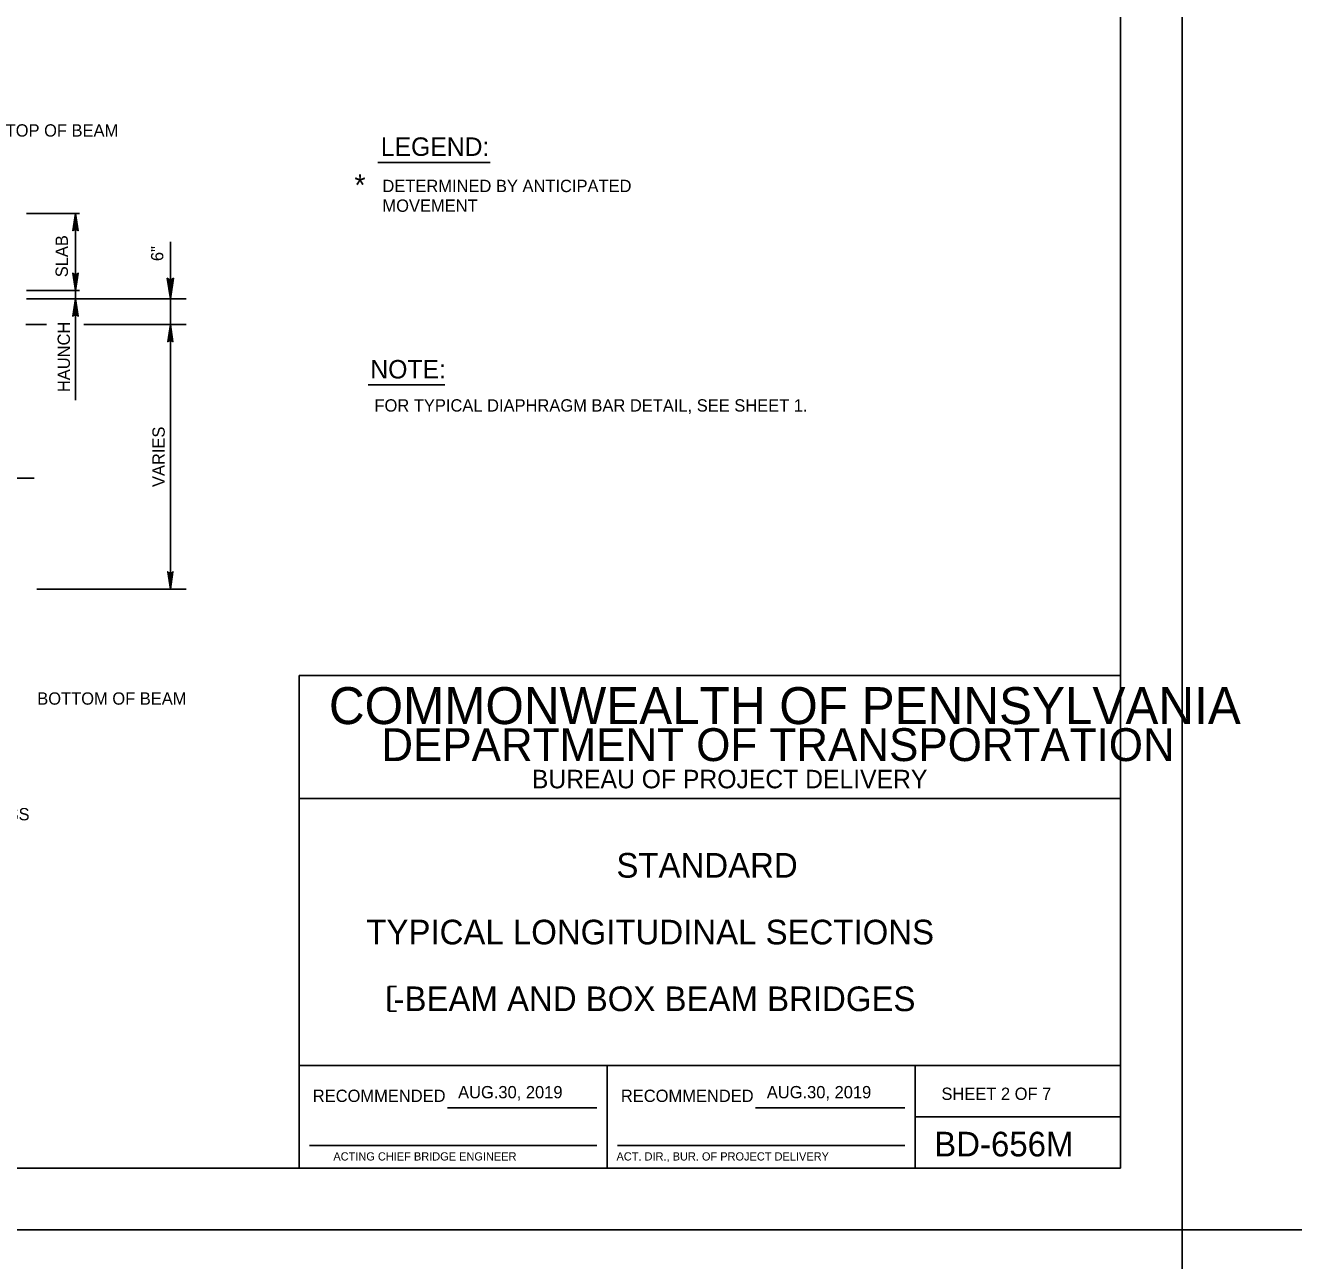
# Model space of a CAD drawing. Extents: x 638653 to 642302, y 298557 to 300414.
# Drawn here: x 640382.5 to 640691.3, y 299737 to 300037.8 of the extents above; entities that cross this region are included whole.
import ezdxf

# ---------------------------------------------------------------- set-up
doc = ezdxf.new("R2010")
doc.units = 0
doc.layers.add('1', color=7, linetype='Continuous')
doc.layers.add('PLT-BNDY', color=7, linetype='Continuous')

msp = doc.modelspace()

# ---------------------------------------------------------------- linework, layer by layer
at = {"layer": '1'}
for p, q in [((640649.16, 300323.52), (640649.16, 299759.52)), ((640468.35, 300004.41), (640495.64, 300004.41)), ((640395.69, 299991.97), (640382.79, 299991.97)), ((640394.72, 299991.97), (640394.72, 299946.54)), ((640417.81, 299985.1), (640417.81, 299971.16)), ((640395.69, 299973.22), (640382.79, 299973.22)), ((640421.66, 299971.16), (640382.79, 299971.16)), ((640417.81, 299971.16), (640417.81, 299964.97)), ((640387.69, 299964.97), (640382.62, 299964.97)), ((640421.66, 299964.97), (640396.76, 299964.97)), ((640417.81, 299964.97), (640417.81, 299900.54)), ((640484.66, 299950.27), (640465.99, 299950.27)), ((640384.63, 299927.53), (640350.17, 299927.53)), ((640649.16, 299923.18), (640649.16, 299872.29)), ((640649.16, 299923.18), (640649.16, 299918.86)), ((640421.66, 299900.54), (640385.34, 299900.54)), ((640649.16, 299879.52), (640449.16, 299879.52)), ((640449.16, 299879.52), (640449.16, 299759.52)), ((640649.16, 299879.52), (640473.77, 299879.52)), ((640649.16, 299879.52), (640473.77, 299879.52)), ((640649.16, 299759.52), (640649.16, 299879.52)), ((640649.16, 299849.52), (640449.16, 299849.52)), ((640471, 299803.77), (640472.88, 299803.77)), ((640471, 299797.77), (640472.88, 299797.77)), ((640649.16, 299784.52), (640449.16, 299784.52)), ((640524.16, 299759.52), (640524.16, 299784.52)), ((640599.16, 299784.52), (640599.16, 299759.52)), ((640485.25, 299774.24), (640521.66, 299774.24)), ((640560.25, 299774.24), (640596.66, 299774.24)), ((640599.16, 299772.02), (640649.16, 299772.02)), ((640451.66, 299765.02), (640521.66, 299765.02)), ((640526.66, 299765.02), (640596.66, 299765.02)), ((640649.16, 299759.52), (639863.16, 299759.52)), ((640449.16, 299759.52), (640649.16, 299759.52)), ((640664.16, 299744.52), (640664.16, 299744.52))]:
    msp.add_line(p, q, dxfattribs=at)
for points in [[(640394.25, 299987.91), (640394.56, 299988.07), (640394.72, 299991.97), (640394.25, 299987.91), (640394.09, 299987.76), (640394.72, 299991.97), (640394.87, 299988.07), (640395.19, 299987.91), (640394.72, 299991.97), (640395.34, 299987.76), (640395.19, 299987.91)], [(640395.19, 299977.29), (640394.87, 299977.13), (640394.72, 299973.22), (640395.19, 299977.29), (640395.34, 299977.44), (640394.72, 299973.22), (640394.56, 299977.13), (640394.25, 299977.29), (640394.72, 299973.22), (640394.09, 299977.44), (640394.25, 299977.29)], [(640418.37, 299976.04), (640417.99, 299975.85), (640417.81, 299971.16), (640418.37, 299976.04), (640418.56, 299976.22), (640417.81, 299971.16), (640417.62, 299975.85), (640417.24, 299976.04), (640417.81, 299971.16), (640417.06, 299976.22), (640417.24, 299976.04)], [(640418.28, 299975.22), (640417.96, 299975.07), (640417.81, 299971.16), (640418.28, 299975.22), (640418.43, 299975.38), (640417.81, 299971.16), (640417.65, 299975.07), (640417.34, 299975.22), (640417.81, 299971.16), (640417.18, 299975.38), (640417.34, 299975.22)], [(640394.25, 299967.1), (640394.56, 299967.26), (640394.72, 299971.16), (640394.25, 299967.1), (640394.09, 299966.94), (640394.72, 299971.16), (640394.87, 299967.26), (640395.19, 299967.1), (640394.72, 299971.16), (640395.34, 299966.94), (640395.19, 299967.1)], [(640417.34, 299960.91), (640417.65, 299961.07), (640417.81, 299964.97), (640417.34, 299960.91), (640417.18, 299960.76), (640417.81, 299964.97), (640417.96, 299961.07), (640418.28, 299960.91), (640417.81, 299964.97), (640418.43, 299960.76), (640418.28, 299960.91)], [(640418.28, 299904.6), (640417.96, 299904.45), (640417.81, 299900.54), (640418.28, 299904.6), (640418.43, 299904.76), (640417.81, 299900.54), (640417.65, 299904.45), (640417.34, 299904.6), (640417.81, 299900.54), (640417.18, 299904.76), (640417.34, 299904.6)]]:
    msp.add_lwpolyline(points, dxfattribs=at)
at = {"layer": 'PLT-BNDY'}
for points in [[(639823.16, 300338.52), (640664.16, 300338.52), (640664.16, 299744.52), (639823.16, 299744.52)], [(640664.16, 300338.52), (641505.16, 300338.52), (641505.16, 299744.52), (640664.16, 299744.52)], [(639823.16, 299744.52), (640664.16, 299744.52), (640664.16, 299150.52), (639823.16, 299150.52)], [(640664.16, 299744.52), (641505.16, 299744.52), (641505.16, 299150.52), (640664.16, 299150.52)]]:
    msp.add_lwpolyline(points, close=True, dxfattribs=at)

# ---------------------------------------------------------------- texts
at = {"layer": '1'}
for s, height, p in [('TOP OF BEAM', 2.9999, (640377.71, 300010.69)), ('LEGEND:', 4.5, (640469.05, 300005.99)), ('*', 5.18, (640462.63, 299996.32)), ('DETERMINED BY ANTICIPATED', 3, (640469.44, 299997.18)), ('MOVEMENT', 3, (640469.44, 299992.38)), ('NOTE:', 4.5, (640466.5, 299951.8)), ('FOR TYPICAL DIAPHRAGM BAR DETAIL, SEE SHEET 1.', 3, (640467.5, 299943.74)), ('BOTTOM OF BEAM', 2.9999, (640385.41, 299872.38)), ('COMMONWEALTH OF PENNSYLVANIA', 9, (640456.41, 299867.65)), ('DEPARTMENT OF TRANSPORTATION', 8.0002, (640469.16, 299858.65)), ('BUREAU OF PROJECT DELIVERY', 4.5, (640505.82, 299852.02)), ('FOR SPANS WITH VERTICAL CLEARANCE LESS', 3, (640291.25, 299844.22)), ('STANDARD', 6, (640526.41, 299830.27)), ('TYPICAL LONGITUDINAL SECTIONS', 6, (640465.53, 299814.02)), ('I-BEAM AND BOX BEAM BRIDGES', 6, (640469.91, 299797.77)), ('RECOMMENDED', 3, (640452.49, 299775.65)), ('AUG.30, 2019', 3, (640487.86, 299776.54)), ('RECOMMENDED', 3, (640527.49, 299775.65)), ('AUG.30, 2019', 3, (640563.02, 299776.54)), ('SHEET 2 OF 7', 3, (640605.53, 299776.15)), ('BD-656M', 6, (640603.78, 299762.4)), ('       ACTING CHIEF BRIDGE ENGINEER', 2.0002, (640452.29, 299761.4)), ('ACT. DIR., BUR. OF PROJECT DELIVERY', 2.0002, (640526.42, 299761.4))]:
    msp.add_text(s, height=height, dxfattribs=at).set_placement(p)
for s, p in [('SLAB', (640392.86, 299976.44)), ('6"', (640416.1, 299980.38)), ('HAUNCH', (640393.36, 299948.47)), ('VARIES', (640416.44, 299925.37))]:
    msp.add_text(s, height=3, rotation=90, dxfattribs=at).set_placement(p)

doc.saveas('drawing.dxf')
